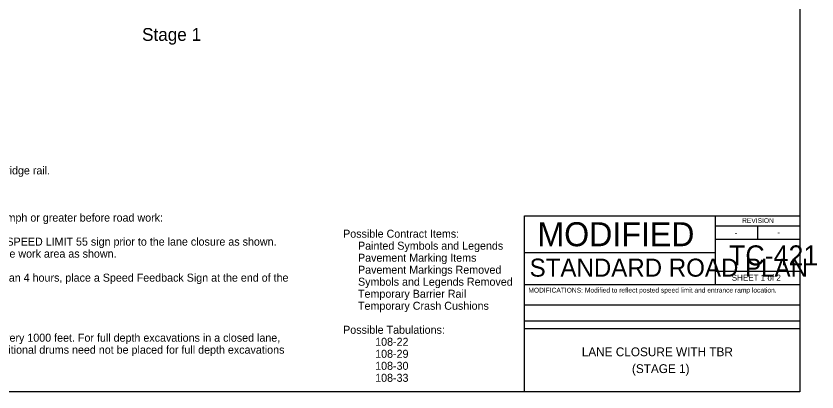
# Model space of a CAD drawing. Extents: x 10133 to 2270741, y 5363 to 1733450.
# Drawn here: x 25709 to 27711, y 7924 to 8863 of the extents above; entities that cross this region are included whole.
import ezdxf

# ---------------------------------------------------------------- set-up
doc = ezdxf.new("R2010")
doc.units = 0
for name, color, linetype in [('dsnStdDimension', 7, 'Continuous'), ('dsnStdShading', 7, 'Continuous'), ('dsnStdTable', 7, 'Continuous'), ('SheetBorder', 7, 'Continuous')]:
    doc.layers.add(name, color=color, linetype=linetype)

msp = doc.modelspace()

# ---------------------------------------------------------------- linework, layer by layer
at = {"layer": 'dsnStdDimension'}
for p, q in [((27456.6, 8364), (27456.6, 8272.7)), ((27456.6, 8339.1), (27667.5, 8339.1)), ((27562.1, 8339.1), (27562.1, 8305.9)), ((27456.6, 8305.9), (27667.5, 8305.9)), ((26979.5, 8272.7), (27456.6, 8272.7)), ((27456.6, 8272.7), (27456.6, 8192.7)), ((27667.5, 8224.9), (27456.6, 8224.9)), ((26979.5, 8192.7), (27667.5, 8192.7)), ((26979.5, 8141.7), (27667.5, 8141.7)), ((26979.5, 8101.7), (27667.5, 8101.7)), ((26979.5, 8082.7), (27667.5, 8082.7))]:
    msp.add_line(p, q, dxfattribs=at)
msp.add_lwpolyline([(26979.5, 8364), (27667.5, 8364), (27667.5, 7924), (26979.5, 7924)], close=True, dxfattribs=at)
at = {"layer": 'SheetBorder'}
msp.add_lwpolyline([(24532.5, 9944), (27667.5, 9944), (27667.5, 7924), (24532.5, 7924)], close=True, dxfattribs=at)

# ---------------------------------------------------------------- texts
at = {"layer": 'dsnStdDimension'}
for s, height, p in [('Stage 1', 32, (26024.1, 8801.1)), ('REVISION', 12, (27523.6, 8346.2)), ('-', 15, (27505.1, 8314.7)), ('-', 15, (27611.6, 8315.1)), ('TC-421', 50, (27490.9, 8240.2)), ('STANDARD ROAD PLAN', 45.001, (26992.6, 8212.1)), ('SHEET 1 of 2', 15, (27497.6, 8202)), ('Modified to reflect posted speed limit and entrance ramp location.', 12, (27130.8, 8172.4)), ('LANE CLOSURE WITH TBR', 22, (27122.9, 8013.3)), ('(STAGE 1)', 22, (27248.3, 7971.3))]:
    msp.add_text(s, height=height, dxfattribs=at).set_placement(p)
at = {"layer": 'dsnStdShading'}
msp.add_text('MODIFICATIONS:', height=12, dxfattribs=at).set_placement((26989.5, 8172.3))
at = {"layer": 'dsnStdTable'}
for s, p in [('Place Concrete Barrier Markers at 10 ft C/C on bridge rail.', (25107.6, 8467.5)), ('For roadways with a posted speed limit of 60 mph or greater before road work:', (25148.9, 8349.6)), ('Possible Contract Items:', (26526.6, 8309.4)), ('Place SPEED LIMIT AHEAD sign and SPEED LIMIT 55 sign prior to the lane closure as shown. ', (25228.9, 8289.6)), ('     Painted Symbols and Legends', (26526.6, 8279.4)), ('Place SPEED LIMIT65 or 70 beyond the work area as shown.', (25228.9, 8259.6)), ('     Pavement Marking Items', (26526.6, 8249.4)), ('     Pavement Markings Removed', (26526.6, 8219.4)), ('For traffic control zones lasting more than 4 hours, place a Speed Feedback Sign at the end of the ', (25228.9, 8199.6)), ('     Symbols and Legends Removed', (26526.6, 8189.4)), ('     Temporary Barrier Rail', (26526.6, 8159.4)), ('     Temporary Crash Cushions', (26526.6, 8129.4)), ('Possible Tabulations:', (26526.6, 8069.4)), ('For lanes closed to traffic, place two drums every 1000 feet. For full depth excavations in a closed lane, ', (25148.9, 8049.6)), ('108-22', (26606.6, 8039.4)), ('place two drums in front of each location. Additional drums need not be placed for full depth excavations ', (25148.9, 8019.6)), ('108-29', (26606.6, 8009.4)), ('108-30', (26606.6, 7979.4)), ('108-33', (26606.6, 7949.4))]:
    msp.add_text(s, height=20, dxfattribs=at).set_placement(p)
at = {"layer": 'SheetBorder'}
msp.add_text('MODIFIED', height=60, dxfattribs=at).set_placement((27012.1, 8288.1))

doc.saveas('drawing.dxf')
